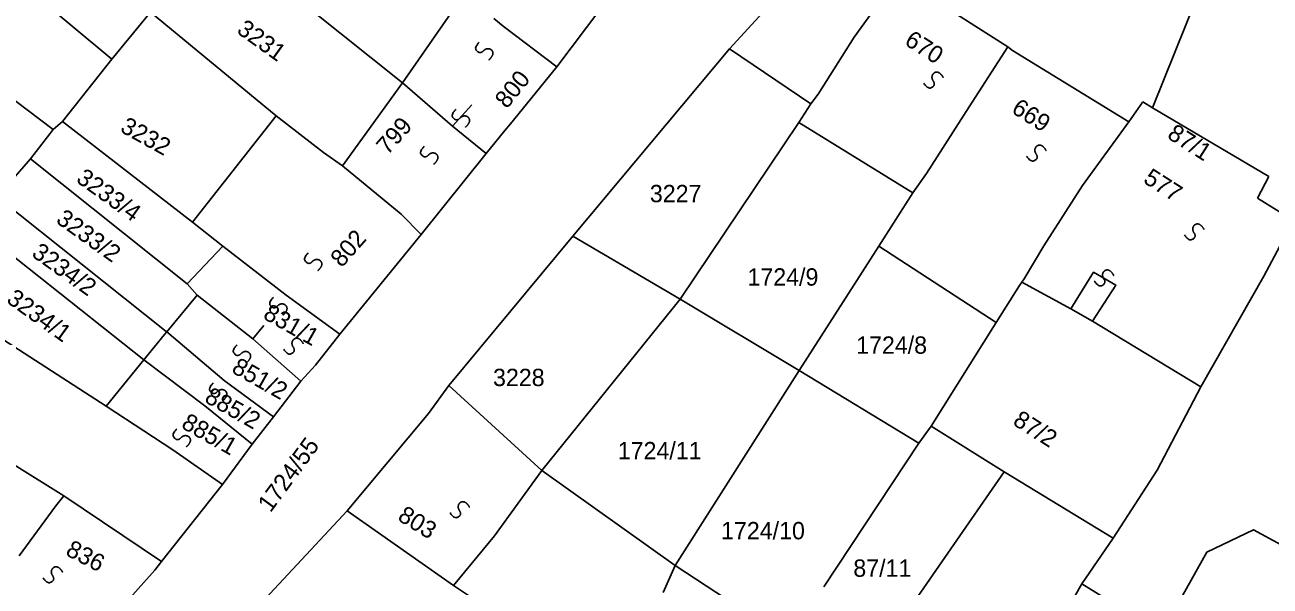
# Model space of a CAD drawing. Extents: x -581999 to -572728, y -1219553 to -1212032.
# Drawn here: x -578351.7 to -578208.2, y -1215792.1 to -1215727.3 of the extents above; entities that cross this region are included whole.
import ezdxf

# ---------------------------------------------------------------- set-up
doc = ezdxf.new("R2010")
doc.units = 0
for name, color, linetype in [('Vrstva 1', 7, 'Continuous'), ('Vrstva 2', 7, 'Continuous'), ('Vrstva 4', 7, 'Continuous'), ('Vrstva 6', 7, 'Continuous')]:
    doc.layers.add(name, color=color, linetype=linetype)

msp = doc.modelspace()

# ---------------------------------------------------------------- linework, layer by layer
at = {"layer": 'Vrstva 1'}
for p, q in [((-578221.723, -1215736.914), (-578202.575, -1215689.196)), ((-578224.43, -1215738.536), (-578222.851, -1215736.211)), ((-578222.851, -1215736.211), (-578221.723, -1215736.914)), ((-578221.723, -1215736.914), (-578208.308, -1215744.829)), ((-578208.308, -1215744.829), (-578209.608, -1215747.342)), ((-578342.349, -1215771.333), (-578363.335, -1215757.809)), ((-578334.695, -1215776.368), (-578342.349, -1215771.333)), ((-578335.97, -1215789.242), (-578328.956, -1215780.368)), ((-578325.082, -1215794.665), (-578314.583, -1215783.383))]:
    msp.add_line(p, q, dxfattribs=at)
for points in [[(-578341.701, -1215731.302), (-578360.036, -1215716.048)], [(-578329.685, -1215716.823), (-578308.206, -1215734.016)], [(-578270.482, -1215730.095), (-578263.645, -1215722.62)], [(-578251.096, -1215721.778), (-578256.104, -1215728.74)], [(-578251.096, -1215721.778), (-578238.409, -1215729.887)], [(-578308.206, -1215734.016), (-578301.098, -1215723.762)], [(-578285.331, -1215725.442), (-578290.395, -1215732.161)], [(-578348.476, -1215739.39), (-578366.198, -1215726.034)], [(-578337.253, -1215725.887), (-578341.701, -1215731.302)], [(-578322.765, -1215737.818), (-578337.253, -1215725.887)], [(-578296.594, -1215727.475), (-578297.647, -1215726.604)], [(-578290.395, -1215732.161), (-578296.594, -1215727.475)], [(-578256.104, -1215728.74), (-578260.285, -1215735.347)], [(-578288.566, -1215751.716), (-578270.482, -1215730.095)], [(-578261.12, -1215736.464), (-578270.482, -1215730.095)], [(-578238.409, -1215729.887), (-578242.868, -1215736.773)], [(-578238.409, -1215729.887), (-578237.864, -1215730.293), (-578224.43, -1215738.536)], [(-578341.701, -1215731.302), (-578347.381, -1215738.501)], [(-578290.395, -1215732.161), (-578295.741, -1215738.753), (-578296.413, -1215739.522)], [(-578315.122, -1215743.588), (-578308.206, -1215734.016)], [(-578302.45, -1215739.022), (-578308.206, -1215734.016)], [(-578260.285, -1215735.347), (-578261.12, -1215736.464)], [(-578261.12, -1215736.464), (-578262.514, -1215738.604)], [(-578242.868, -1215736.773), (-578247.791, -1215744.497)], [(-578332.414, -1215750.088), (-578322.765, -1215737.818)], [(-578317.308, -1215742.07), (-578322.765, -1215737.818)], [(-578348.476, -1215739.39), (-578351.085, -1215742.797)], [(-578347.381, -1215738.501), (-578348.476, -1215739.39)], [(-578347.381, -1215738.501), (-578332.414, -1215750.088)], [(-578298.537, -1215742.167), (-578302.45, -1215739.022)], [(-578296.413, -1215739.522), (-578298.537, -1215742.167)], [(-578262.514, -1215738.604), (-578276.167, -1215758.982)], [(-578262.514, -1215738.604), (-578249.37, -1215746.729)], [(-578229.804, -1215745.854), (-578224.43, -1215738.536)], [(-578315.122, -1215743.588), (-578317.308, -1215742.07)], [(-578298.537, -1215742.167), (-578306.036, -1215751.515)], [(-578353.344, -1215745.401), (-578351.085, -1215742.797)], [(-578351.085, -1215742.797), (-578333.043, -1215757.208)], [(-578308.358, -1215749.173), (-578315.122, -1215743.588)], [(-578247.791, -1215744.497), (-578249.37, -1215746.729)], [(-578249.37, -1215746.729), (-578253.271, -1215752.871)], [(-578234.263, -1215752.832), (-578229.804, -1215745.854)], [(-578335.388, -1215762.732), (-578335.437, -1215762.691), (-578354.781, -1215747.321)], [(-578209.608, -1215747.342), (-578205.477, -1215749.921)], [(-578306.036, -1215751.515), (-578308.358, -1215749.173)], [(-578205.477, -1215749.921), (-578208.899, -1215756.332)], [(-578357.45, -1215750.611), (-578338.039, -1215765.987)], [(-578332.414, -1215750.088), (-578328.929, -1215752.846)], [(-578315.41, -1215763.028), (-578306.036, -1215751.515)], [(-578302.866, -1215768.923), (-578288.566, -1215751.716)], [(-578276.167, -1215758.982), (-578288.566, -1215751.716)], [(-578328.929, -1215752.846), (-578333.043, -1215757.208)], [(-578328.929, -1215752.846), (-578321.618, -1215758.5)], [(-578253.271, -1215752.871), (-578262.466, -1215767.2)], [(-578253.271, -1215752.871), (-578239.743, -1215761.671)], [(-578236.786, -1215757.008), (-578236.523, -1215756.626), (-578234.263, -1215752.832)], [(-578239.743, -1215761.671), (-578237.05, -1215757.391), (-578236.786, -1215757.008)], [(-578236.786, -1215757.008), (-578231.151, -1215760.09)], [(-578208.899, -1215756.332), (-578216.145, -1215769.079)], [(-578331.882, -1215758.516), (-578335.388, -1215762.732)], [(-578333.043, -1215757.208), (-578331.882, -1215758.516)], [(-578325.456, -1215763.544), (-578331.882, -1215758.516)], [(-578321.618, -1215758.5), (-578315.41, -1215763.028)], [(-578276.167, -1215758.982), (-578292.118, -1215778.739)], [(-578262.466, -1215767.2), (-578276.167, -1215758.982)], [(-578231.151, -1215760.09), (-578228.649, -1215761.495)], [(-578335.388, -1215762.732), (-578335.644, -1215763.04), (-578338.039, -1215765.987)], [(-578328.741, -1215768.344), (-578335.388, -1215762.732)], [(-578239.743, -1215761.671), (-578247.251, -1215773.64), (-578248.644, -1215775.593)], [(-578228.649, -1215761.495), (-578216.145, -1215769.079)], [(-578319.925, -1215768.442), (-578325.456, -1215763.544)], [(-578318.215, -1215766.592), (-578315.41, -1215763.028)], [(-578338.039, -1215765.987), (-578342.349, -1215771.333)], [(-578338.039, -1215765.987), (-578330.999, -1215771.29)], [(-578319.925, -1215768.442), (-578318.215, -1215766.592)], [(-578323.072, -1215772.554), (-578328.741, -1215768.344)], [(-578323.072, -1215772.554), (-578319.925, -1215768.442)], [(-578262.466, -1215767.2), (-578276.753, -1215789.682)], [(-578248.644, -1215775.593), (-578262.466, -1215767.2)], [(-578305.216, -1215772.164), (-578302.866, -1215768.923)], [(-578292.118, -1215778.739), (-578302.866, -1215768.923)], [(-578216.145, -1215769.079), (-578221.195, -1215778.69)], [(-578330.999, -1215771.29), (-578325.535, -1215775.707)], [(-578325.535, -1215775.707), (-578323.072, -1215772.554)], [(-578302.325, -1215791.994), (-578314.583, -1215783.383), (-578305.216, -1215772.164)], [(-578347.257, -1215781.666), (-578359.055, -1215774.327)], [(-578238.821, -1215778.882), (-578247.251, -1215773.64)], [(-578328.956, -1215780.368), (-578325.535, -1215775.707)], [(-578248.644, -1215775.593), (-578259.602, -1215792.151)], [(-578328.956, -1215780.368), (-578334.695, -1215776.368)], [(-578292.118, -1215778.739), (-578297.597, -1215786.273)], [(-578276.753, -1215789.682), (-578292.118, -1215778.739)], [(-578251.82, -1215797.67), (-578238.821, -1215778.882)], [(-578238.821, -1215778.882), (-578226.267, -1215786.543)], [(-578226.267, -1215786.543), (-578221.195, -1215778.69)], [(-578348.159, -1215782.805), (-578352.398, -1215788.587)], [(-578348.159, -1215782.805), (-578347.257, -1215781.666)], [(-578336.766, -1215790.241), (-578335.97, -1215789.242), (-578347.257, -1215781.666)], [(-578201.443, -1215790.286), (-578210.075, -1215785.563), (-578215.455, -1215788.156), (-578220.697, -1215797.517)], [(-578297.597, -1215786.273), (-578302.325, -1215791.994)], [(-578229.866, -1215791.81), (-578226.267, -1215786.543)], [(-578278.147, -1215792.82), (-578276.753, -1215789.682)], [(-578276.753, -1215789.682), (-578270.823, -1215793.585), (-578272.401, -1215796.19)], [(-578341.196, -1215795.228), (-578336.766, -1215790.241)], [(-578299.101, -1215794.162), (-578302.325, -1215791.994)], [(-578229.866, -1215791.81), (-578231.995, -1215795.54), (-578239.244, -1215806.132)], [(-578220.697, -1215797.517), (-578229.866, -1215791.81)]]:
    msp.add_lwpolyline(points, dxfattribs=at)
at = {"layer": 'Vrstva 4'}
for points in [[(-578300.196, -1215736.571), (-578302.45, -1215739.022)], [(-578231.151, -1215760.09), (-578228.516, -1215755.875), (-578225.963, -1215757.351), (-578228.649, -1215761.495)], [(-578325.456, -1215763.544), (-578324.202, -1215762.027)]]:
    msp.add_lwpolyline(points, dxfattribs=at)
at = {"layer": 'Vrstva 6'}
for points in [[(-578299.339, -1215729.316), (-578299.926, -1215729.938), (-578299.471, -1215730.547), (-578299.065, -1215730.535), (-578298.779, -1215730.23), (-578298.473, -1215730.076), (-578298.173, -1215730.092), (-578297.966, -1215730.194), (-578297.79, -1215730.397), (-578297.745, -1215730.761), (-578298.08, -1215731.273), (-578298.238, -1215731.365)], [(-578248.098, -1215734.053), (-578247.618, -1215734.76), (-578246.924, -1215734.449), (-578246.847, -1215734.049), (-578247.083, -1215733.704), (-578247.168, -1215733.372), (-578247.086, -1215733.082), (-578246.942, -1215732.902), (-578246.706, -1215732.774), (-578246.341, -1215732.81), (-578245.914, -1215733.249), (-578245.859, -1215733.422)], [(-578302.034, -1215737.071), (-578302.621, -1215737.693), (-578302.166, -1215738.302), (-578301.76, -1215738.29), (-578301.474, -1215737.985), (-578301.168, -1215737.831), (-578300.868, -1215737.847), (-578300.661, -1215737.949), (-578300.485, -1215738.152), (-578300.44, -1215738.516), (-578300.775, -1215739.028), (-578300.933, -1215739.12)], [(-578236.233, -1215742.475), (-578235.753, -1215743.182), (-578235.059, -1215742.871), (-578234.982, -1215742.471), (-578235.218, -1215742.126), (-578235.303, -1215741.794), (-578235.221, -1215741.504), (-578235.077, -1215741.324), (-578234.841, -1215741.196), (-578234.476, -1215741.232), (-578234.049, -1215741.671), (-578233.994, -1215741.844)], [(-578305.684, -1215741.34), (-578306.271, -1215741.962), (-578305.816, -1215742.571), (-578305.41, -1215742.559), (-578305.124, -1215742.254), (-578304.818, -1215742.1), (-578304.518, -1215742.116), (-578304.311, -1215742.218), (-578304.135, -1215742.421), (-578304.09, -1215742.785), (-578304.425, -1215743.297), (-578304.583, -1215743.389)], [(-578218.028, -1215751.563), (-578217.548, -1215752.27), (-578216.854, -1215751.959), (-578216.777, -1215751.559), (-578217.013, -1215751.214), (-578217.098, -1215750.882), (-578217.016, -1215750.592), (-578216.872, -1215750.412), (-578216.636, -1215750.284), (-578216.271, -1215750.32), (-578215.844, -1215750.759), (-578215.789, -1215750.932)], [(-578319.069, -1215753.625), (-578319.656, -1215754.247), (-578319.201, -1215754.856), (-578318.795, -1215754.844), (-578318.509, -1215754.539), (-578318.203, -1215754.385), (-578317.903, -1215754.401), (-578317.696, -1215754.503), (-578317.52, -1215754.706), (-578317.475, -1215755.07), (-578317.81, -1215755.582), (-578317.968, -1215755.674)], [(-578228.433, -1215756.872), (-578227.953, -1215757.579), (-578227.259, -1215757.268), (-578227.182, -1215756.868), (-578227.418, -1215756.523), (-578227.503, -1215756.191), (-578227.421, -1215755.901), (-578227.277, -1215755.721), (-578227.041, -1215755.593), (-578226.676, -1215755.629), (-578226.249, -1215756.068), (-578226.194, -1215756.241)], [(-578323.085, -1215758.752), (-578323.672, -1215759.374), (-578323.217, -1215759.983), (-578322.811, -1215759.971), (-578322.525, -1215759.666), (-578322.219, -1215759.512), (-578321.919, -1215759.528), (-578321.712, -1215759.63), (-578321.536, -1215759.833), (-578321.491, -1215760.197), (-578321.826, -1215760.709), (-578321.984, -1215760.801)], [(-578327.284, -1215764.244), (-578327.871, -1215764.866), (-578327.416, -1215765.475), (-578327.01, -1215765.463), (-578326.724, -1215765.158), (-578326.418, -1215765.004), (-578326.118, -1215765.02), (-578325.911, -1215765.122), (-578325.735, -1215765.325), (-578325.69, -1215765.689), (-578326.025, -1215766.201), (-578326.183, -1215766.293)], [(-578321.893, -1215764.745), (-578321.413, -1215765.452), (-578320.719, -1215765.141), (-578320.642, -1215764.741), (-578320.878, -1215764.396), (-578320.963, -1215764.064), (-578320.881, -1215763.774), (-578320.737, -1215763.594), (-578320.501, -1215763.466), (-578320.136, -1215763.502), (-578319.709, -1215763.941), (-578319.654, -1215764.114)], [(-578330.022, -1215768.638), (-578330.609, -1215769.26), (-578330.154, -1215769.869), (-578329.748, -1215769.857), (-578329.462, -1215769.552), (-578329.156, -1215769.398), (-578328.856, -1215769.414), (-578328.649, -1215769.516), (-578328.473, -1215769.719), (-578328.428, -1215770.083), (-578328.763, -1215770.595), (-578328.921, -1215770.687)], [(-578334.22, -1215773.948), (-578334.807, -1215774.57), (-578334.352, -1215775.179), (-578333.946, -1215775.167), (-578333.66, -1215774.862), (-578333.354, -1215774.708), (-578333.054, -1215774.724), (-578332.847, -1215774.826), (-578332.671, -1215775.029), (-578332.626, -1215775.393), (-578332.961, -1215775.905), (-578333.119, -1215775.997)], [(-578302.727, -1215783.602), (-578302.247, -1215784.309), (-578301.553, -1215783.998), (-578301.476, -1215783.598), (-578301.712, -1215783.253), (-578301.797, -1215782.921), (-578301.715, -1215782.631), (-578301.571, -1215782.451), (-578301.335, -1215782.323), (-578300.97, -1215782.359), (-578300.543, -1215782.798), (-578300.488, -1215782.971)], [(-578349.639, -1215791.109), (-578349.159, -1215791.816), (-578348.465, -1215791.505), (-578348.388, -1215791.105), (-578348.624, -1215790.76), (-578348.709, -1215790.428), (-578348.627, -1215790.138), (-578348.483, -1215789.958), (-578348.247, -1215789.83), (-578347.882, -1215789.866), (-578347.455, -1215790.305), (-578347.4, -1215790.478)]]:
    msp.add_open_spline(points, degree=2, dxfattribs=at)

# ---------------------------------------------------------------- texts
at = {"layer": 'Vrstva 2'}
for s, rotation, p in [('3231', 324.40504, (-578327.424, -1215728.195)), ('670', 327.47703, (-578250.434, -1215729.545)), ('800', 51.10968, (-578296.158, -1215737.101)), ('669', 327.47703, (-578238.1, -1215737.393)), ('3232', 330.99845, (-578340.868, -1215739.599)), ('799', 48.40522, (-578309.909, -1215742.437)), ('87/1', 327.47703, (-578220.141, -1215740.325)), ('3233/4', 324.40504, (-578345.944, -1215745.373)), ('577', 327.47703, (-578222.899, -1215745.457)), ('3233/2', 324.40504, (-578348.273, -1215750.07)), ('802', 48.40522, (-578315.201, -1215755.414)), ('3234/2', 324.40504, (-578351.077, -1215753.955)), ('3234/1', 324.40504, (-578353.974, -1215759.275)), ('831/1', 330.49128, (-578324.398, -1215761.142)), ('851/2', 330.49128, (-578328.026, -1215767.355)), ('885/2', 330.49128, (-578331.157, -1215770.76)), ('885/1', 330.49128, (-578333.823, -1215773.762)), ('87/2', 327.47703, (-578237.943, -1215773.374)), ('1724/55', 53.74004, (-578323.416, -1215783.678)), ('803', 328.31145, (-578308.88, -1215784.391)), ('836', 332.33615, (-578347.166, -1215788.429))]:
    msp.add_text(s, height=2, rotation=rotation, dxfattribs=at).set_placement(p)
for s, p in [('3227', (-578279.674, -1215747.794)), ('1724/9', (-578268.421, -1215757.416)), ('1724/8', (-578255.894, -1215765.271)), ('3228', (-578297.761, -1215769.003)), ('1724/11', (-578283.376, -1215777.447)), ('1724/10', (-578271.469, -1215786.676)), ('87/11', (-578256.214, -1215790.997))]:
    msp.add_text(s, height=2, dxfattribs=at).set_placement(p)

doc.saveas('drawing.dxf')
